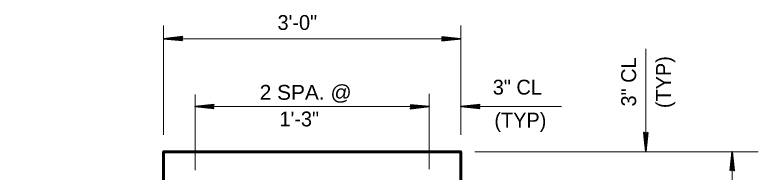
# Model space of a CAD drawing. Extents: x 14.14 to 17.34, y -1.61 to 0.38.
# Drawn here: x 15.5046 to 15.9213, y -0.8807 to -0.7925 of the extents above; entities that cross this region are included whole.
import ezdxf

# ---------------------------------------------------------------- set-up
doc = ezdxf.new("R2010")
doc.units = 0
doc.header["$LTSCALE"] = 0.0033
doc.layers.add('1', color=7, linetype='Continuous', lineweight=40)

msp = doc.modelspace()

# ---------------------------------------------------------------- linework, layer by layer
at = {"layer": '1', "lineweight": 13}
for p, q in [((15.587917, -0.859833), (15.587917, -0.798583)), ((15.754583, -0.859833), (15.754583, -0.798583)), ((15.588167, -0.805917), (15.754583, -0.805917)), ((15.85825, -0.859167), (15.85825, -0.811583)), ((15.605583, -0.879583), (15.605583, -0.83725)), ((15.736917, -0.879083), (15.736917, -0.836917)), ((15.605417, -0.844), (15.736333, -0.844)), ((15.7645, -0.844), (15.811, -0.844)), ((15.7625, -0.869333), (15.92125, -0.869333)), ((15.906667, -1.285167), (15.906667, -0.869417))]:
    msp.add_line(p, q, dxfattribs=at)
at = {"layer": '1', "lineweight": 35}
for p, q in [((15.5985, -0.805917), (15.587917, -0.805917)), ((15.59825, -0.80675), (15.590417, -0.80575)), ((15.59825, -0.80675), (15.590417, -0.805917)), ((15.59825, -0.806917), (15.590417, -0.806)), ((15.59825, -0.806917), (15.590417, -0.806)), ((15.59825, -0.806833), (15.590417, -0.806)), ((15.59825, -0.804833), (15.590917, -0.805667)), ((15.59825, -0.805), (15.590917, -0.80575)), ((15.59825, -0.805083), (15.590917, -0.805917)), ((15.598333, -0.80525), (15.591, -0.806)), ((15.744, -0.805917), (15.754583, -0.805917)), ((15.744167, -0.806583), (15.7515, -0.805833)), ((15.74425, -0.804917), (15.752083, -0.805833)), ((15.74425, -0.804917), (15.752083, -0.805833)), ((15.74425, -0.805), (15.752083, -0.805833)), ((15.74425, -0.805083), (15.752083, -0.805917)), ((15.74425, -0.805083), (15.752083, -0.806083)), ((15.74425, -0.80675), (15.751583, -0.805917)), ((15.74425, -0.806833), (15.751583, -0.806083)), ((15.74425, -0.807), (15.751583, -0.806167)), ((15.616167, -0.844), (15.605583, -0.844)), ((15.615917, -0.844833), (15.608083, -0.843833)), ((15.615917, -0.844833), (15.608083, -0.844)), ((15.615917, -0.845), (15.608083, -0.844083)), ((15.615917, -0.845), (15.608083, -0.844083)), ((15.615917, -0.844917), (15.608083, -0.844083)), ((15.615917, -0.842917), (15.608583, -0.84375)), ((15.615917, -0.843083), (15.608583, -0.843833)), ((15.615917, -0.843167), (15.608583, -0.844)), ((15.616, -0.843333), (15.608667, -0.844083)), ((15.726333, -0.844), (15.736917, -0.844)), ((15.7265, -0.844667), (15.733833, -0.843917)), ((15.726583, -0.843), (15.734417, -0.843917)), ((15.726583, -0.843), (15.734417, -0.843917)), ((15.726583, -0.843083), (15.734417, -0.843917)), ((15.726583, -0.843167), (15.734417, -0.844)), ((15.726583, -0.843167), (15.734417, -0.844167)), ((15.726583, -0.844833), (15.733917, -0.844)), ((15.726583, -0.844917), (15.733917, -0.844167)), ((15.726583, -0.845083), (15.733917, -0.84425)), ((15.765167, -0.844), (15.754583, -0.844)), ((15.764917, -0.844833), (15.757083, -0.843833)), ((15.764917, -0.844833), (15.757083, -0.844)), ((15.764917, -0.845), (15.757083, -0.844083)), ((15.764917, -0.845), (15.757083, -0.844083)), ((15.764917, -0.844917), (15.757083, -0.844083)), ((15.764917, -0.842917), (15.757583, -0.84375)), ((15.764917, -0.843083), (15.757583, -0.843833)), ((15.764917, -0.843167), (15.757583, -0.844)), ((15.765, -0.843333), (15.757667, -0.844083)), ((15.857167, -0.85875), (15.858, -0.866083)), ((15.857333, -0.85875), (15.858083, -0.866083)), ((15.857417, -0.85875), (15.85825, -0.866083)), ((15.857583, -0.858667), (15.858333, -0.866)), ((15.859083, -0.85875), (15.858083, -0.866583)), ((15.85825, -0.8585), (15.85825, -0.869083)), ((15.859083, -0.85875), (15.85825, -0.866583)), ((15.85925, -0.85875), (15.858333, -0.866583)), ((15.85925, -0.85875), (15.858333, -0.866583)), ((15.859167, -0.85875), (15.858333, -0.866583)), ((15.906667, -0.879917), (15.906667, -0.869333)), ((15.905667, -0.879667), (15.906583, -0.871833)), ((15.905667, -0.879667), (15.906583, -0.871833)), ((15.90575, -0.879667), (15.906583, -0.871833)), ((15.905833, -0.879667), (15.906667, -0.871833)), ((15.905833, -0.879667), (15.906833, -0.871833)), ((15.907333, -0.87975), (15.906583, -0.872417)), ((15.9075, -0.879667), (15.906667, -0.872333)), ((15.907583, -0.879667), (15.906833, -0.872333)), ((15.90775, -0.879667), (15.906917, -0.872333))]:
    msp.add_line(p, q, dxfattribs=at)
for points in [[(15.5985, -0.807), (15.587917, -0.805917), (15.5985, -0.80475), (15.597917, -0.805917)], [(15.59775, -0.806), (15.593083, -0.806083), (15.593083, -0.806), (15.594, -0.806), (15.59775, -0.806083), (15.59475, -0.806167), (15.597917, -0.80625), (15.595667, -0.806333), (15.597917, -0.806417), (15.594417, -0.806167), (15.58975, -0.806), (15.590667, -0.80575), (15.589417, -0.80575), (15.59775, -0.80575), (15.595333, -0.805583), (15.597917, -0.805583), (15.592583, -0.806), (15.597917, -0.805333)], [(15.744, -0.804833), (15.754583, -0.805917), (15.744, -0.807083), (15.744583, -0.805917)], [(15.74475, -0.805833), (15.749417, -0.80575), (15.749417, -0.805833), (15.7485, -0.805833), (15.74475, -0.80575), (15.74775, -0.805667), (15.744583, -0.805583), (15.746833, -0.8055), (15.744583, -0.805417), (15.748083, -0.805667), (15.75275, -0.805833), (15.751833, -0.806083), (15.753083, -0.806083), (15.74475, -0.806083), (15.747167, -0.80625), (15.744583, -0.80625), (15.749917, -0.805833), (15.744583, -0.8065)], [(15.616167, -0.845083), (15.605583, -0.844), (15.616167, -0.842833), (15.615583, -0.844)], [(15.615417, -0.844083), (15.61075, -0.844167), (15.61075, -0.844083), (15.611667, -0.844083), (15.615417, -0.844167), (15.612417, -0.84425), (15.615583, -0.844333), (15.613333, -0.844417), (15.615583, -0.8445), (15.612083, -0.84425), (15.607417, -0.844083), (15.608333, -0.843833), (15.607083, -0.843833), (15.615417, -0.843833), (15.613, -0.843667), (15.615583, -0.843667), (15.61025, -0.844083), (15.615583, -0.843417)], [(15.726333, -0.842917), (15.736917, -0.844), (15.726333, -0.845167), (15.726917, -0.844)], [(15.727083, -0.843917), (15.73175, -0.843833), (15.73175, -0.843917), (15.730833, -0.843917), (15.727083, -0.843833), (15.730083, -0.84375), (15.726917, -0.843667), (15.729167, -0.843583), (15.726917, -0.8435), (15.730417, -0.84375), (15.735083, -0.843917), (15.734167, -0.844167), (15.735417, -0.844167), (15.727083, -0.844167), (15.7295, -0.844333), (15.726917, -0.844333), (15.73225, -0.843917), (15.726917, -0.844583)], [(15.765167, -0.845083), (15.754583, -0.844), (15.765167, -0.842833), (15.764583, -0.844)], [(15.764417, -0.844083), (15.75975, -0.844167), (15.75975, -0.844083), (15.760667, -0.844083), (15.764417, -0.844167), (15.761417, -0.84425), (15.764583, -0.844333), (15.762333, -0.844417), (15.764583, -0.8445), (15.761083, -0.84425), (15.756417, -0.844083), (15.757333, -0.843833), (15.756083, -0.843833), (15.764417, -0.843833), (15.762, -0.843667), (15.764583, -0.843667), (15.75925, -0.844083), (15.764583, -0.843417)], [(15.859333, -0.8585), (15.85825, -0.869083), (15.857083, -0.8585), (15.85825, -0.859083)], [(15.858333, -0.85925), (15.858417, -0.863917), (15.858333, -0.863917), (15.858333, -0.863), (15.858417, -0.85925), (15.8585, -0.86225), (15.858583, -0.859083), (15.858667, -0.861333), (15.85875, -0.859083), (15.8585, -0.862583), (15.858333, -0.86725), (15.858083, -0.866333), (15.858083, -0.867583), (15.858083, -0.85925), (15.857917, -0.861667), (15.857917, -0.859083), (15.858333, -0.864417), (15.857667, -0.859083)], [(15.905583, -0.879917), (15.906667, -0.869333), (15.907833, -0.879917), (15.906667, -0.879333)], [(15.906583, -0.879167), (15.9065, -0.8745), (15.906583, -0.8745), (15.906583, -0.875417), (15.9065, -0.879167), (15.906417, -0.876167), (15.906333, -0.879333), (15.90625, -0.877083), (15.906167, -0.879333), (15.906417, -0.875833), (15.906583, -0.871167), (15.906833, -0.872083), (15.906833, -0.870833), (15.906833, -0.879167), (15.907, -0.87675), (15.907, -0.879333), (15.906583, -0.874), (15.90725, -0.879333)]]:
    msp.add_lwpolyline(points, close=True, dxfattribs=at)
for points in [[(15.59775, -0.806), (15.598167, -0.80675), (15.597917, -0.8065), (15.59775, -0.806167), (15.5975, -0.80625), (15.597667, -0.806583), (15.597833, -0.805833), (15.598, -0.805333), (15.59825, -0.804917)], [(15.74475, -0.805833), (15.744333, -0.805083), (15.744583, -0.805333), (15.74475, -0.805667), (15.745, -0.805583), (15.744833, -0.80525), (15.744667, -0.806), (15.7445, -0.8065), (15.74425, -0.806917)], [(15.615417, -0.844083), (15.615833, -0.844833), (15.615583, -0.844583), (15.615417, -0.84425), (15.615167, -0.844333), (15.615333, -0.844667), (15.6155, -0.843917), (15.615667, -0.843417), (15.615917, -0.843)], [(15.727083, -0.843917), (15.726667, -0.843167), (15.726917, -0.843417), (15.727083, -0.84375), (15.727333, -0.843667), (15.727167, -0.843333), (15.727, -0.844083), (15.726833, -0.844583), (15.726583, -0.845)], [(15.764417, -0.844083), (15.764833, -0.844833), (15.764583, -0.844583), (15.764417, -0.84425), (15.764167, -0.844333), (15.764333, -0.844667), (15.7645, -0.843917), (15.764667, -0.843417), (15.764917, -0.843)], [(15.858333, -0.85925), (15.859083, -0.858833), (15.858833, -0.859083), (15.8585, -0.85925), (15.858583, -0.8595), (15.858917, -0.859333), (15.858167, -0.859167), (15.857667, -0.859), (15.85725, -0.85875)], [(15.906583, -0.879167), (15.905833, -0.879583), (15.906083, -0.879333), (15.906417, -0.879167), (15.906333, -0.878917), (15.906, -0.879083), (15.90675, -0.87925), (15.90725, -0.879417), (15.907667, -0.879667)]]:
    msp.add_lwpolyline(points, dxfattribs=at)
at = {"layer": '1', "lineweight": 60}
msp.add_lwpolyline([(15.504583, -1.202667), (15.587917, -1.202667), (15.587917, -0.869333), (15.754583, -0.869333), (15.754583, -1.202667), (15.837917, -1.202667)], dxfattribs=at)

# ---------------------------------------------------------------- texts
at = {"layer": '1'}
for s, height, p in [('3\'-0"', 0.008333, (15.651833, -0.801)), ('3" CL', 0.008334, (15.7725, -0.83725)), ('1\'-3"', 0.008334, (15.652917, -0.855083)), ('(TYP)', 0.008334, (15.773417, -0.85575))]:
    msp.add_text(s, height=height, dxfattribs=at).set_placement(p)
for s, p in [('(TYP)', (15.872333, -0.844833)), ('3" CL', (15.852833, -0.843917))]:
    msp.add_text(s, height=0.008334, rotation=90, dxfattribs=at).set_placement(p)
at = {"layer": '1', "width": 1.05}
msp.add_text('2 SPA. @ ', height=0.008334, dxfattribs=at).set_placement((15.641833, -0.840167))

doc.saveas('drawing.dxf')
